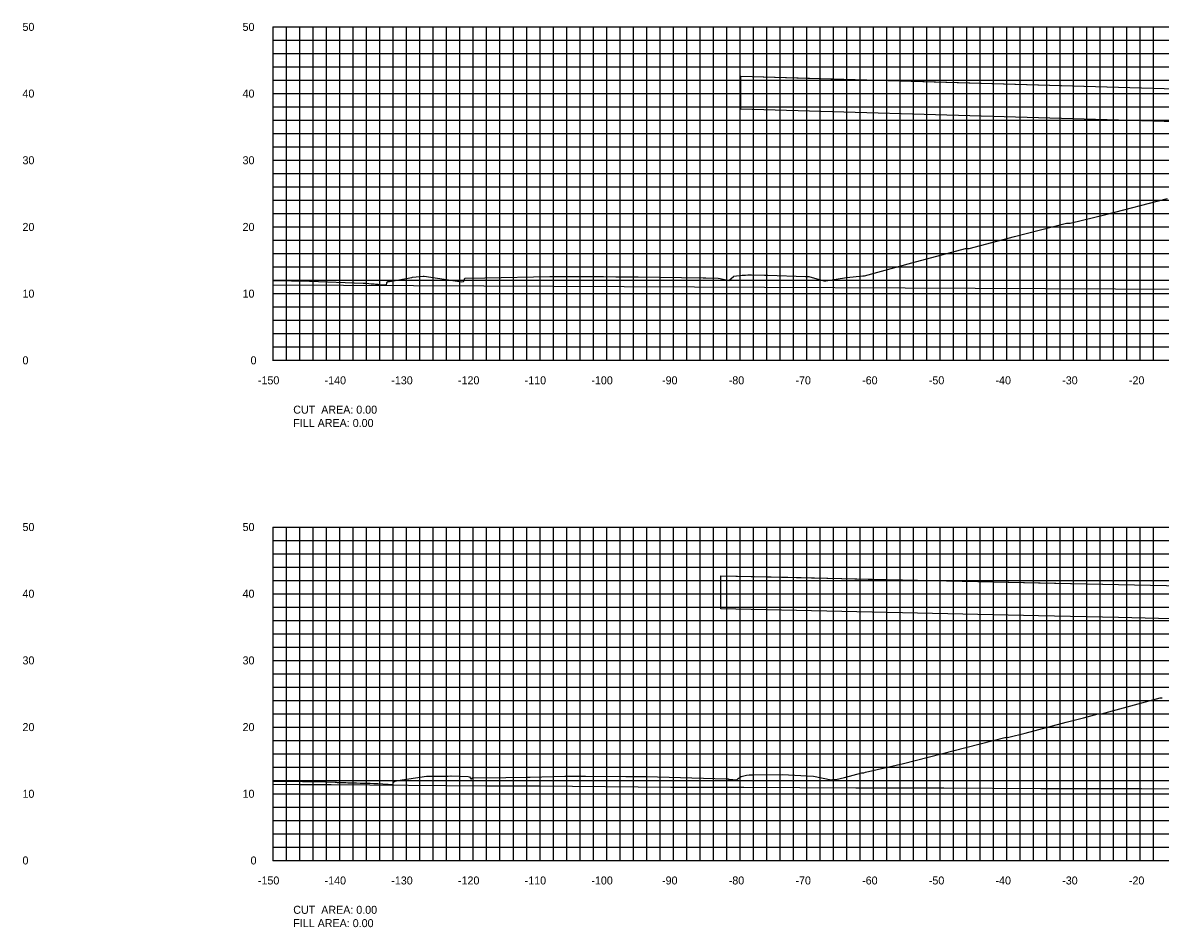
# Model space of a CAD drawing. Extents: x 1800880 to 1814006, y 250083 to 250560.
# Drawn here: x 1810603.4 to 1810774, y 250089.4 to 250225 of the extents above; entities that cross this region are included whole.
import ezdxf

# ---------------------------------------------------------------- set-up
doc = ezdxf.new("R2010")
doc.units = 0
for name, color, linetype in [('33', 7, 'Continuous'), ('CL-CNST', 7, 'Continuous'), ('DESIGN - DRAINAGE - Bridges', 7, 'Continuous'), ('DRAINAGETXT', 7, 'Continuous'), ('Level 46', 7, 'Continuous'), ('Level 62', 7, 'Continuous'), ('TOPO', 7, 'Continuous')]:
    doc.layers.add(name, color=color, linetype=linetype)

msp = doc.modelspace()

# ---------------------------------------------------------------- linework, layer by layer
at = {"layer": 'CL-CNST'}
for points in [[(1810641, 250186.38), (1810646.42, 250186.3), (1810654.49, 250186.02), (1810654.76, 250186.01), (1810654.91, 250185.99), (1810655.35, 250185.95), (1810655.68, 250185.92), (1810655.94, 250185.9), (1810656.15, 250185.88), (1810656.33, 250185.86), (1810656.47, 250185.85), (1810656.59, 250185.84), (1810656.7, 250185.83), (1810656.79, 250185.82), (1810656.86, 250185.81), (1810656.87, 250185.81), (1810656.94, 250185.81), (1810657.94, 250185.75), (1810658, 250185.7), (1810658.05, 250186.06), (1810658.18, 250186.27), (1810658.41, 250186.27), (1810661.77, 250186.87), (1810661.87, 250186.88), (1810663.46, 250187.05), (1810663.62, 250187.05), (1810669.28, 250186.22), (1810669.5, 250186.24), (1810669.53, 250186.2), (1810669.59, 250186.33), (1810669.75, 250186.77), (1810672.72, 250186.82), (1810682.45, 250186.99), (1810683.45, 250187.02), (1810685.94, 250187.01), (1810686.83, 250187), (1810687.25, 250187), (1810687.3, 250187), (1810687.69, 250187), (1810689.89, 250186.99), (1810690.23, 250186.98), (1810690.52, 250186.98), (1810692.36, 250186.97), (1810695.7, 250186.96), (1810705.46, 250186.8), (1810705.86, 250186.8), (1810707.71, 250186.77), (1810707.99, 250186.72), (1810709.32, 250186.39), (1810709.99, 250187), (1810710.01, 250187.02), (1810710.01, 250187.02), (1810710.01, 250187.02), (1810710.02, 250187.02), (1810710.06, 250187.03), (1810711.3, 250187.2), (1810711.55, 250187.2), (1810711.82, 250187.2), (1810712.17, 250187.24), (1810712.73, 250187.24), (1810714.67, 250187.22), (1810715.15, 250187.21), (1810720.8, 250186.98), (1810721.17, 250186.98), (1810721.32, 250186.98), (1810723.56, 250186.33), (1810723.88, 250186.33), (1810726.94, 250186.87), (1810729.43, 250187.1), (1810729.68, 250187.1), (1810736.75, 250189.03), (1810744.79, 250191.19), (1810745.03, 250191.2), (1810745.34, 250191.21), (1810752.17, 250192.99), (1810759.96, 250194.99), (1810760.1, 250194.99), (1810760.47, 250195), (1810765.84, 250196.3), (1810775.07, 250198.72)], [(1810641, 250111.34), (1810645.41, 250111.28), (1810647.38, 250111.26), (1810650.29, 250111.15), (1810650.43, 250111.15), (1810650.58, 250111.14), (1810650.75, 250111.14), (1810650.93, 250111.13), (1810651.13, 250111.12), (1810651.35, 250111.12), (1810651.6, 250111.11), (1810651.88, 250111.1), (1810652.2, 250111.09), (1810652.56, 250111.08), (1810652.93, 250111.06), (1810652.98, 250111.06), (1810653.46, 250111.05), (1810654.03, 250111.04), (1810654.71, 250111.02), (1810655.54, 250111.01), (1810656.09, 250110.99), (1810656.21, 250110.99), (1810656.4, 250110.98), (1810656.56, 250110.97), (1810656.7, 250110.96), (1810658.96, 250110.84), (1810658.98, 250110.81), (1810659.05, 250111.24), (1810659.08, 250111.24), (1810659.27, 250111.38), (1810659.5, 250111.38), (1810659.66, 250111.44), (1810663.97, 250112.06), (1810664.13, 250112.07), (1810664.21, 250112.07), (1810664.61, 250112.07), (1810664.64, 250112.07), (1810664.64, 250112.07), (1810664.64, 250112.07), (1810667.15, 250112.09), (1810667.21, 250112.09), (1810667.65, 250112.1), (1810667.7, 250112.1), (1810670.23, 250112.01), (1810670.44, 250111.96), (1810670.67, 250111.63), (1810670.67, 250111.63), (1810670.68, 250111.63), (1810670.68, 250111.64), (1810670.69, 250111.64), (1810670.69, 250111.65), (1810670.7, 250111.66), (1810670.71, 250111.67), (1810670.72, 250111.68), (1810670.72, 250111.69), (1810670.73, 250111.69), (1810670.74, 250111.7), (1810670.75, 250111.71), (1810670.76, 250111.73), (1810670.77, 250111.74), (1810670.79, 250111.75), (1810670.8, 250111.77), (1810670.81, 250111.79), (1810670.83, 250111.81), (1810670.85, 250111.83), (1810670.86, 250111.84), (1810675.89, 250111.88), (1810678.94, 250111.9), (1810678.99, 250111.9), (1810679.36, 250111.9), (1810679.46, 250111.9), (1810679.47, 250111.9), (1810679.47, 250111.9), (1810679.51, 250111.9), (1810684.7, 250112.05), (1810686.21, 250112.05), (1810687.31, 250112.05), (1810687.83, 250112.05), (1810693.85, 250112.03), (1810694.89, 250112.03), (1810695.09, 250112.03), (1810695.3, 250112.03), (1810696.92, 250112.02), (1810707.19, 250111.74), (1810708.93, 250111.69), (1810708.94, 250111.69), (1810709.04, 250111.67), (1810709.13, 250111.66), (1810709.21, 250111.65), (1810709.28, 250111.63), (1810709.34, 250111.62), (1810710.51, 250111.54), (1810710.72, 250111.7), (1810711.18, 250112.04), (1810711.77, 250112.18), (1810711.98, 250112.22), (1810712.36, 250112.25), (1810712.54, 250112.28), (1810712.57, 250112.28), (1810712.88, 250112.28), (1810717.31, 250112.32), (1810722.02, 250112.06), (1810724.67, 250111.53), (1810724.85, 250111.55), (1810725.27, 250111.55), (1810725.36, 250111.55), (1810726.68, 250111.88), (1810729.28, 250112.58), (1810729.55, 250112.58), (1810729.79, 250112.65), (1810735.52, 250113.96), (1810750.71, 250117.88), (1810750.79, 250117.89), (1810751.28, 250117.9), (1810753.76, 250118.54), (1810759.91, 250120.17), (1810761.91, 250120.68), (1810762.5, 250120.83), (1810764.68, 250121.41), (1810765.17, 250121.42), (1810765.19, 250121.42), (1810773.97, 250123.8), (1810774.31, 250123.8)]]:
    msp.add_lwpolyline(points, dxfattribs=at)
at = {"layer": 'DESIGN - DRAINAGE - Bridges'}
for p, q in [((1810640.94, 250224.43), (1810641, 250224.43)), ((1810641, 250174.43), (1810641, 250224.43)), ((1810640.94, 250214.43), (1810641, 250214.43)), ((1810640.94, 250204.43), (1810641, 250204.43)), ((1810640.94, 250194.43), (1810641, 250194.43)), ((1810640.94, 250184.43), (1810641, 250184.43)), ((1810640.94, 250174.43), (1810641, 250174.43)), ((1810641, 250174.43), (1810941, 250174.43)), ((1810641, 250174.37), (1810641, 250174.43)), ((1810651, 250174.37), (1810651, 250174.43)), ((1810661, 250174.37), (1810661, 250174.43)), ((1810671, 250174.37), (1810671, 250174.43)), ((1810681, 250174.37), (1810681, 250174.43)), ((1810691, 250174.37), (1810691, 250174.43)), ((1810701, 250174.37), (1810701, 250174.43)), ((1810711, 250174.37), (1810711, 250174.43)), ((1810721, 250174.37), (1810721, 250174.43)), ((1810731, 250174.37), (1810731, 250174.43)), ((1810741, 250174.37), (1810741, 250174.43)), ((1810751, 250174.37), (1810751, 250174.43)), ((1810761, 250174.37), (1810761, 250174.43)), ((1810771, 250174.37), (1810771, 250174.43)), ((1810640.94, 250149.43), (1810641, 250149.43)), ((1810641, 250099.43), (1810641, 250149.43)), ((1810640.94, 250139.43), (1810641, 250139.43)), ((1810640.94, 250129.43), (1810641, 250129.43)), ((1810640.94, 250119.43), (1810641, 250119.43)), ((1810640.94, 250109.43), (1810641, 250109.43)), ((1810640.94, 250099.43), (1810641, 250099.43)), ((1810641, 250099.43), (1810941, 250099.43)), ((1810641, 250099.37), (1810641, 250099.43)), ((1810651, 250099.37), (1810651, 250099.43)), ((1810661, 250099.37), (1810661, 250099.43)), ((1810671, 250099.37), (1810671, 250099.43)), ((1810681, 250099.37), (1810681, 250099.43)), ((1810691, 250099.37), (1810691, 250099.43)), ((1810701, 250099.37), (1810701, 250099.43)), ((1810711, 250099.37), (1810711, 250099.43)), ((1810721, 250099.37), (1810721, 250099.43)), ((1810731, 250099.37), (1810731, 250099.43)), ((1810741, 250099.37), (1810741, 250099.43)), ((1810751, 250099.37), (1810751, 250099.43)), ((1810761, 250099.37), (1810761, 250099.43)), ((1810771, 250099.37), (1810771, 250099.43))]:
    msp.add_line(p, q, dxfattribs=at)
at = {"layer": 'Level 46'}
for p, q in [((1810641, 250224.43), (1810941, 250224.43)), ((1810641, 250174.43), (1810641, 250224.43)), ((1810643, 250174.43), (1810643, 250224.43)), ((1810645, 250174.43), (1810645, 250224.43)), ((1810647, 250174.43), (1810647, 250224.43)), ((1810649, 250174.43), (1810649, 250224.43)), ((1810651, 250174.43), (1810651, 250224.43)), ((1810653, 250174.43), (1810653, 250224.43)), ((1810655, 250174.43), (1810655, 250224.43)), ((1810657, 250174.43), (1810657, 250224.43)), ((1810659, 250174.43), (1810659, 250224.43)), ((1810661, 250174.43), (1810661, 250224.43)), ((1810663, 250174.43), (1810663, 250224.43)), ((1810665, 250174.43), (1810665, 250224.43)), ((1810667, 250174.43), (1810667, 250224.43)), ((1810669, 250174.43), (1810669, 250224.43)), ((1810671, 250174.43), (1810671, 250224.43)), ((1810673, 250174.43), (1810673, 250224.43)), ((1810675, 250174.43), (1810675, 250224.43)), ((1810677, 250174.43), (1810677, 250224.43)), ((1810679, 250174.43), (1810679, 250224.43)), ((1810681, 250174.43), (1810681, 250224.43)), ((1810683, 250174.43), (1810683, 250224.43)), ((1810685, 250174.43), (1810685, 250224.43)), ((1810687, 250174.43), (1810687, 250224.43)), ((1810689, 250174.43), (1810689, 250224.43)), ((1810691, 250174.43), (1810691, 250224.43)), ((1810693, 250174.43), (1810693, 250224.43)), ((1810695, 250174.43), (1810695, 250224.43)), ((1810697, 250174.43), (1810697, 250224.43)), ((1810699, 250174.43), (1810699, 250224.43)), ((1810701, 250174.43), (1810701, 250224.43)), ((1810703, 250174.43), (1810703, 250224.43)), ((1810705, 250174.43), (1810705, 250224.43)), ((1810707, 250174.43), (1810707, 250224.43)), ((1810709, 250174.43), (1810709, 250224.43)), ((1810711, 250174.43), (1810711, 250224.43)), ((1810713, 250174.43), (1810713, 250224.43)), ((1810715, 250174.43), (1810715, 250224.43)), ((1810717, 250174.43), (1810717, 250224.43)), ((1810719, 250174.43), (1810719, 250224.43)), ((1810721, 250174.43), (1810721, 250224.43)), ((1810723, 250174.43), (1810723, 250224.43)), ((1810725, 250174.43), (1810725, 250224.43)), ((1810727, 250174.43), (1810727, 250224.43)), ((1810729, 250174.43), (1810729, 250224.43)), ((1810731, 250174.43), (1810731, 250224.43)), ((1810733, 250174.43), (1810733, 250224.43)), ((1810735, 250174.43), (1810735, 250224.43)), ((1810737, 250174.43), (1810737, 250224.43)), ((1810739, 250174.43), (1810739, 250224.43)), ((1810741, 250174.43), (1810741, 250224.43)), ((1810743, 250174.43), (1810743, 250224.43)), ((1810745, 250174.43), (1810745, 250224.43)), ((1810747, 250174.43), (1810747, 250224.43)), ((1810749, 250174.43), (1810749, 250224.43)), ((1810751, 250174.43), (1810751, 250224.43)), ((1810753, 250174.43), (1810753, 250224.43)), ((1810755, 250174.43), (1810755, 250224.43)), ((1810757, 250174.43), (1810757, 250224.43)), ((1810759, 250174.43), (1810759, 250224.43)), ((1810761, 250174.43), (1810761, 250224.43)), ((1810763, 250174.43), (1810763, 250224.43)), ((1810765, 250174.43), (1810765, 250224.43)), ((1810767, 250174.43), (1810767, 250224.43)), ((1810769, 250174.43), (1810769, 250224.43)), ((1810771, 250174.43), (1810771, 250224.43)), ((1810773, 250174.43), (1810773, 250224.43)), ((1810641, 250222.43), (1810941, 250222.43)), ((1810641, 250220.43), (1810941, 250220.43)), ((1810641, 250218.43), (1810941, 250218.43)), ((1810641, 250216.43), (1810941, 250216.43)), ((1810641, 250214.43), (1810941, 250214.43)), ((1810641, 250212.43), (1810941, 250212.43)), ((1810641, 250210.43), (1810941, 250210.43)), ((1810641, 250208.43), (1810941, 250208.43)), ((1810641, 250206.43), (1810941, 250206.43)), ((1810641, 250204.43), (1810941, 250204.43)), ((1810641, 250202.43), (1810941, 250202.43)), ((1810641, 250200.43), (1810941, 250200.43)), ((1810641, 250198.43), (1810941, 250198.43)), ((1810641, 250196.43), (1810941, 250196.43)), ((1810641, 250194.43), (1810941, 250194.43)), ((1810641, 250192.43), (1810941, 250192.43)), ((1810641, 250190.43), (1810941, 250190.43)), ((1810641, 250188.43), (1810941, 250188.43)), ((1810641, 250186.43), (1810941, 250186.43)), ((1810641, 250184.43), (1810941, 250184.43)), ((1810641, 250182.43), (1810941, 250182.43)), ((1810641, 250180.43), (1810941, 250180.43)), ((1810641, 250178.43), (1810941, 250178.43)), ((1810641, 250176.43), (1810941, 250176.43)), ((1810641, 250174.43), (1810941, 250174.43)), ((1810641, 250149.43), (1810941, 250149.43)), ((1810641, 250099.43), (1810641, 250149.43)), ((1810643, 250099.43), (1810643, 250149.43)), ((1810645, 250099.43), (1810645, 250149.43)), ((1810647, 250099.43), (1810647, 250149.43)), ((1810649, 250099.43), (1810649, 250149.43)), ((1810651, 250099.43), (1810651, 250149.43)), ((1810653, 250099.43), (1810653, 250149.43)), ((1810655, 250099.43), (1810655, 250149.43)), ((1810657, 250099.43), (1810657, 250149.43)), ((1810659, 250099.43), (1810659, 250149.43)), ((1810661, 250099.43), (1810661, 250149.43)), ((1810663, 250099.43), (1810663, 250149.43)), ((1810665, 250099.43), (1810665, 250149.43)), ((1810667, 250099.43), (1810667, 250149.43)), ((1810669, 250099.43), (1810669, 250149.43)), ((1810671, 250099.43), (1810671, 250149.43)), ((1810673, 250099.43), (1810673, 250149.43)), ((1810675, 250099.43), (1810675, 250149.43)), ((1810677, 250099.43), (1810677, 250149.43)), ((1810679, 250099.43), (1810679, 250149.43)), ((1810681, 250099.43), (1810681, 250149.43)), ((1810683, 250099.43), (1810683, 250149.43)), ((1810685, 250099.43), (1810685, 250149.43)), ((1810687, 250099.43), (1810687, 250149.43)), ((1810689, 250099.43), (1810689, 250149.43)), ((1810691, 250099.43), (1810691, 250149.43)), ((1810693, 250099.43), (1810693, 250149.43)), ((1810695, 250099.43), (1810695, 250149.43)), ((1810697, 250099.43), (1810697, 250149.43)), ((1810699, 250099.43), (1810699, 250149.43)), ((1810701, 250099.43), (1810701, 250149.43)), ((1810703, 250099.43), (1810703, 250149.43)), ((1810705, 250099.43), (1810705, 250149.43)), ((1810707, 250099.43), (1810707, 250149.43)), ((1810709, 250099.43), (1810709, 250149.43)), ((1810711, 250099.43), (1810711, 250149.43)), ((1810713, 250099.43), (1810713, 250149.43)), ((1810715, 250099.43), (1810715, 250149.43)), ((1810717, 250099.43), (1810717, 250149.43)), ((1810719, 250099.43), (1810719, 250149.43)), ((1810721, 250099.43), (1810721, 250149.43)), ((1810723, 250099.43), (1810723, 250149.43)), ((1810725, 250099.43), (1810725, 250149.43)), ((1810727, 250099.43), (1810727, 250149.43)), ((1810729, 250099.43), (1810729, 250149.43)), ((1810731, 250099.43), (1810731, 250149.43)), ((1810733, 250099.43), (1810733, 250149.43)), ((1810735, 250099.43), (1810735, 250149.43)), ((1810737, 250099.43), (1810737, 250149.43)), ((1810739, 250099.43), (1810739, 250149.43)), ((1810741, 250099.43), (1810741, 250149.43)), ((1810743, 250099.43), (1810743, 250149.43)), ((1810745, 250099.43), (1810745, 250149.43)), ((1810747, 250099.43), (1810747, 250149.43)), ((1810749, 250099.43), (1810749, 250149.43)), ((1810751, 250099.43), (1810751, 250149.43)), ((1810753, 250099.43), (1810753, 250149.43)), ((1810755, 250099.43), (1810755, 250149.43)), ((1810757, 250099.43), (1810757, 250149.43)), ((1810759, 250099.43), (1810759, 250149.43)), ((1810761, 250099.43), (1810761, 250149.43)), ((1810763, 250099.43), (1810763, 250149.43)), ((1810765, 250099.43), (1810765, 250149.43)), ((1810767, 250099.43), (1810767, 250149.43)), ((1810769, 250099.43), (1810769, 250149.43)), ((1810771, 250099.43), (1810771, 250149.43)), ((1810773, 250099.43), (1810773, 250149.43)), ((1810641, 250147.43), (1810941, 250147.43)), ((1810641, 250145.43), (1810941, 250145.43)), ((1810641, 250143.43), (1810941, 250143.43)), ((1810641, 250141.43), (1810941, 250141.43)), ((1810641, 250139.43), (1810941, 250139.43)), ((1810641, 250137.43), (1810941, 250137.43)), ((1810641, 250135.43), (1810941, 250135.43)), ((1810641, 250133.43), (1810941, 250133.43)), ((1810641, 250131.43), (1810941, 250131.43)), ((1810641, 250129.43), (1810941, 250129.43)), ((1810641, 250127.43), (1810941, 250127.43)), ((1810641, 250125.43), (1810941, 250125.43)), ((1810641, 250123.43), (1810941, 250123.43)), ((1810641, 250121.43), (1810941, 250121.43)), ((1810641, 250119.43), (1810941, 250119.43)), ((1810641, 250117.43), (1810941, 250117.43)), ((1810641, 250115.43), (1810941, 250115.43)), ((1810641, 250113.43), (1810941, 250113.43)), ((1810641, 250111.43), (1810941, 250111.43)), ((1810641, 250109.43), (1810941, 250109.43)), ((1810641, 250107.43), (1810941, 250107.43)), ((1810641, 250105.43), (1810941, 250105.43)), ((1810641, 250103.43), (1810941, 250103.43)), ((1810641, 250101.43), (1810941, 250101.43)), ((1810641, 250099.43), (1810941, 250099.43))]:
    msp.add_line(p, q, dxfattribs=at)
at = {"layer": 'Level 62'}
msp.add_line((1810641, 250185.77), (1810941, 250184.27), dxfattribs=at)
for points in [[(1810711.1, 250217.03), (1810721.15, 250216.74), (1810733.21, 250216.39), (1810767.75, 250215.39), (1810779.75, 250215.04), (1810789.75, 250214.75), (1810791, 250214.71)], [(1810708.1, 250142.11), (1810718.16, 250141.89), (1810730.22, 250141.63), (1810767.75, 250140.8), (1810779.75, 250140.54), (1810789.75, 250140.32), (1810791, 250140.29)], [(1810641, 250110.88), (1810645.09, 250110.84), (1810649.7, 250110.82), (1810672.85, 250110.64), (1810680.99, 250110.61), (1810700.6, 250110.43), (1810711.54, 250110.41), (1810728.36, 250110.3), (1810741.56, 250110.3), (1810756.12, 250110.2), (1810771.2, 250110.22), (1810783.87, 250110.13), (1810800.53, 250110.19), (1810811.63, 250110.15), (1810829.64, 250110.24), (1810839.38, 250110.25), (1810858.55, 250110.36), (1810867.14, 250110.2), (1810887.32, 250110.32), (1810894.89, 250110.41), (1810901.87, 250110.36), (1810922.65, 250110.49), (1810929.3, 250110.6), (1810941, 250110.67)]]:
    msp.add_lwpolyline(points, dxfattribs=at)
at = {"layer": 'TOPO'}
for points in [[(1810755.75, 250210.78), (1810711.1, 250212.07), (1810711.1, 250217.03), (1810755.75, 250215.74), (1810767.75, 250215.39), (1810779.75, 250215.04), (1810789.75, 250214.75), (1810791, 250214.71), (1810791, 250209.75), (1810789.75, 250209.79), (1810779.75, 250210.08), (1810767.75, 250210.43)], [(1810755.75, 250136.1), (1810708.1, 250137.15), (1810708.1, 250142.11), (1810755.75, 250141.06), (1810767.75, 250140.8), (1810779.75, 250140.54), (1810789.75, 250140.32), (1810791, 250140.29), (1810791, 250135.33), (1810789.75, 250135.36), (1810779.75, 250135.58), (1810767.75, 250135.84)]]:
    msp.add_lwpolyline(points, close=True, dxfattribs=at)

# ---------------------------------------------------------------- texts
for s, p in [('-150', (1810638.7, 250170.83)), ('-140', (1810648.7, 250170.83)), ('-130', (1810658.7, 250170.83)), ('-120', (1810668.7, 250170.83)), ('-110', (1810678.7, 250170.83)), ('-100', (1810688.7, 250170.83)), ('-90', (1810699.3, 250170.83)), ('-80', (1810709.3, 250170.83)), ('-70', (1810719.3, 250170.83)), ('-60', (1810729.3, 250170.83)), ('-50', (1810739.3, 250170.83)), ('-40', (1810749.3, 250170.83)), ('-30', (1810759.3, 250170.83)), ('-20', (1810769.3, 250170.83)), ('-150', (1810638.7, 250095.83)), ('-140', (1810648.7, 250095.83)), ('-130', (1810658.7, 250095.83)), ('-120', (1810668.7, 250095.83)), ('-110', (1810678.7, 250095.83)), ('-100', (1810688.7, 250095.83)), ('-90', (1810699.3, 250095.83)), ('-80', (1810709.3, 250095.83)), ('-70', (1810719.3, 250095.83)), ('-60', (1810729.3, 250095.83)), ('-50', (1810739.3, 250095.83)), ('-40', (1810749.3, 250095.83)), ('-30', (1810759.3, 250095.83)), ('-20', (1810769.3, 250095.83))]:
    msp.add_text(s, height=1.2).set_placement(p)
at = {"layer": '33'}
for s, p in [('50', (1810603.4, 250223.83)), ('50', (1810636.4, 250223.83)), ('40', (1810603.4, 250213.83)), ('40', (1810636.4, 250213.83)), ('30', (1810603.4, 250203.83)), ('30', (1810636.4, 250203.83)), ('20', (1810603.4, 250193.83)), ('20', (1810636.4, 250193.83)), ('10', (1810603.4, 250183.83)), ('10', (1810636.4, 250183.83)), ('0', (1810603.4, 250173.83)), ('0', (1810637.6, 250173.83)), ('50', (1810603.4, 250148.83)), ('50', (1810636.4, 250148.83)), ('40', (1810603.4, 250138.83)), ('40', (1810636.4, 250138.83)), ('30', (1810603.4, 250128.83)), ('30', (1810636.4, 250128.83)), ('20', (1810603.4, 250118.83)), ('20', (1810636.4, 250118.83)), ('10', (1810603.4, 250108.83)), ('10', (1810636.4, 250108.83)), ('0', (1810603.4, 250098.83)), ('0', (1810637.6, 250098.83))]:
    msp.add_text(s, height=1.2, dxfattribs=at).set_placement(p)
at = {"layer": 'DESIGN - DRAINAGE - Bridges'}
for p in [(1810641, 250174.43), (1810641, 250099.43)]:
    msp.add_text('-', height=0.0001, dxfattribs=at).set_placement(p)
at = {"layer": 'DRAINAGETXT'}
for s, p in [('CUT  AREA: 0.00', (1810644, 250166.43)), ('FILL AREA: 0.00', (1810644, 250164.43)), ('CUT  AREA: 0.00', (1810644, 250091.43)), ('FILL AREA: 0.00', (1810644, 250089.43))]:
    msp.add_text(s, height=1.2, dxfattribs=at).set_placement(p)

doc.saveas('drawing.dxf')
